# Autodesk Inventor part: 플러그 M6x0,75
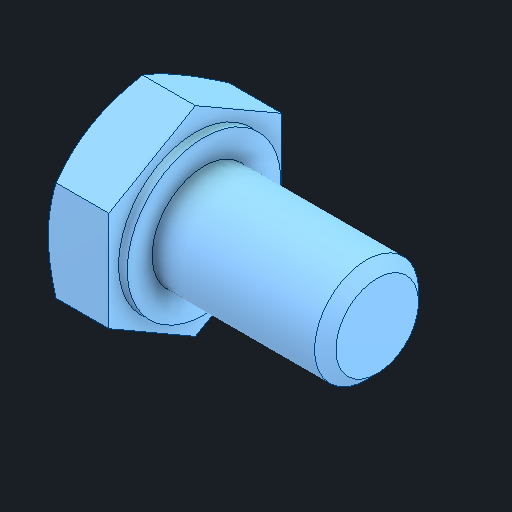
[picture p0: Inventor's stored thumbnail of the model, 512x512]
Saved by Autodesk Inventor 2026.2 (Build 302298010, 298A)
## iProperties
Created: 2026-03
Part Number: 플러그 M6x0,75
Material: 강철, 연강
Description: 6각 머리 볼트 및 6각 머리 나사
Document SubType Name: Modeling
Designer: PC2-02
Density: 7.85 g/cm^3
Appearance: 기본값
Author: jhkim
Sending System: Autodesk Inventor 2026
Preprocessor: ST-DEVELOPER v20.1
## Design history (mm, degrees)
feature "Solid1"
node "솔리드1"
